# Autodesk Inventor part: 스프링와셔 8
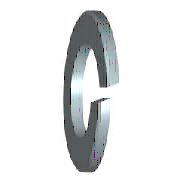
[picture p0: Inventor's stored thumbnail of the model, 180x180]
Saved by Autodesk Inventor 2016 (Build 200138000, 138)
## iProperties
IsCustomPart: 1
Created: 2012-02
Part Number: 스프링와셔 8
Material: 강철, 연강
Description: 스프링 잠금 와셔
Document SubType Name: Modeling
Standard: KS B 1324
Designer: mduedu
Standards Organization: KS
Language: ko-KR
Size Designation: 번호 3 - 8
Categories: <MemberInstance><Categories><Category DisplayName="조임쇠" InternalName="e4da775c-781d-43d5-af7c-5136215cf5a6" Mnemonic="FSTN"><Category DisplayName="와셔" InternalN
Density: 1 g/cm^3
Appearance: 파란색 - 벽 페인트 - 광택
Author: mduedu
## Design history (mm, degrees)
sketch "스케치1"
  geometry: C1 r 7.4 at (0, 0); C2 r 4.1 at (0, 0); 1 further point
  constraints: 2 centre point, 2 coincident
  dimensions: "d0" = 8.2 diameter of C2 (= SD1); "d1" = 14.8 diameter of C1 (= SD2)
extrude "본체" new body sketch "스케치1" distance "d2" = 2.5 (= SD); taper "d3" = 0 deg
sketch "스케치2"
  geometry: L1 (0, -4.1)-(0, 4.1) reference; L2 (2.5, 7.4)-(2.5, -7.4) reference; L3 (-1.2, 0)-(7.2, 0) reference; L4 (0, -0.5)-(2.5, 0.41); L5 (0, 0.5)-(2.5, 1.41)
  constraints: 4 end point, 4 point on line, 1 parallel
  dimensions: "d4" = 0.5 distance from line of L3 L4.start (= 0.2 x SD); "d5" = 0.5 distance from line of L3 L5.start (= 0.2 x SD); "d6" = 70 deg angle of L2 L4 (= FAWI)
extrude "절단부" cut sketch "스케치2" stored distance "d7" = 2.5 (= SD); taper "d8" = 0 deg
workaxis "Work Axis1"
workplane "Work Plane1"
body "Solid1"
other parameters: "SD1" = 8.2 [user parameter; used in 1 equation term], "SD2" = 14.8 [user parameter; used in 1 equation term], "SD" = 2.5 [user parameter; used in 4 equation terms], "FAWI" = 70 deg [user parameter; used in 1 equation term], "d9" = 0, "d10" = 0, "d11" = 0, "d12" = 0, "SDI" = 3.3 [user parameter], "NND" = 8 [user parameter]
